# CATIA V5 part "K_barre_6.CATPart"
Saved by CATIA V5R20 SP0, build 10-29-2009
Part number: barre_6
Bounding box of the stored display mesh (mm): x -43.04 to 2.493, y -13 to -10, z 34.495 to 58.999
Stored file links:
  G:\Khaled_CFAO_2011\ST2M\ST2M_GR2\gcausse\Khaled\CAD_ThinkMotion\K_barre_6.CATPart
  C:\Documents and Settings\gcausse\Bureau\video thinkmotio\assemblage_gcausse\pupitre_think.CATProduct
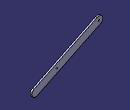
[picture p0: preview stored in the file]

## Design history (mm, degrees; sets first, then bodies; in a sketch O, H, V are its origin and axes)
Set1
  Sketch1 on Plane1, origin (0, -11, 0), H (-1, 0, 0), V (0, 0, 1)
    line L1 (39.4627, 58.7585) -> (-1.0843, 39.2408)
    arc A1 centre (0, 36.9882) radius 2.5 from (-1.0843, 39.2408) to (1.0843, 34.7356) ccw
    point P3 (0, 36.9882)
    line L2 (1.0843, 34.7356) -> (41.6313, 54.2533)
    arc A2 centre (40.547, 56.5059) radius 2.5 from (41.6313, 54.2533) to (39.4627, 58.7585) ccw
    point P6 (40.547, 56.5059)
    reference projected point E1 (40.547, 56.5059) from Point1
    reference projected line E2 (0, 36.9882) -> (40.547, 56.5059) from Line1
    reference projected line E3 (0, 36.9882) -> (40.547, 56.5059) from Line1
    reference projected point E4 (0, 36.9882) from Point2
    distance L1 L2 = 5
    tangency: A1 L1, L2 A1, A2 L1, A2 L2
    coincidence: P6 E1, P3 E4
    parallelism: L1 E2, L2 E3
Set2
  Plane1: linked copy from another document
  Point1: linked copy from another document
  Line1: linked copy from another document
  Point2: linked copy from another document
  Point3: linked copy from another document
Set3
  Point4: type Center, Curve edge [end face of Pad2 | face of Pad2 from Sketch4.A1]
Body1 (main body)
  Pad1: profile Sketch1, direction (0, 1, 0), length 1
  Sketch2 on start face of Pad1, origin (-35.4548, -11, 55.0707), H (1, 0, 0), V (0, 0, 1)
    point P1 (-5.0921, 1.4352)
    reference projected point E1 (-5.0921, 1.4352) from Point1
    coincidence: P1 E1
  Hole1: placed by Sketch2, at (-40.547, -11, 56.5059) direction (0, 1, 0), diameter 1, depth 1
  Sketch3 on start face of Pad1, origin (-14.913, -11, 46.5966), H (1, 0, 0), V (0, 0, 1)
    point P1 (1.3973, -3.1025)
    reference projected point E1 (1.3973, -3.1025) from Point3
    coincidence: P1 E1
  Hole2: placed by Sketch3, at (-13.5157, -11, 43.4941) direction (0, 1, 0), diameter 1, depth 1
  Sketch4 on start face of Pad1, origin (0, -11, 0), H (-1, 0, 0), V (0, 0, 1)
    circle A1 centre (0, 36.9882) radius 0.5
    point P1 (0, 36.9882)
    reference projected point E1 (0, 36.9882) from Point2
    coincidence: P1 E1
  Pad2: profile Sketch4, direction (0, -1, 0), length 2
